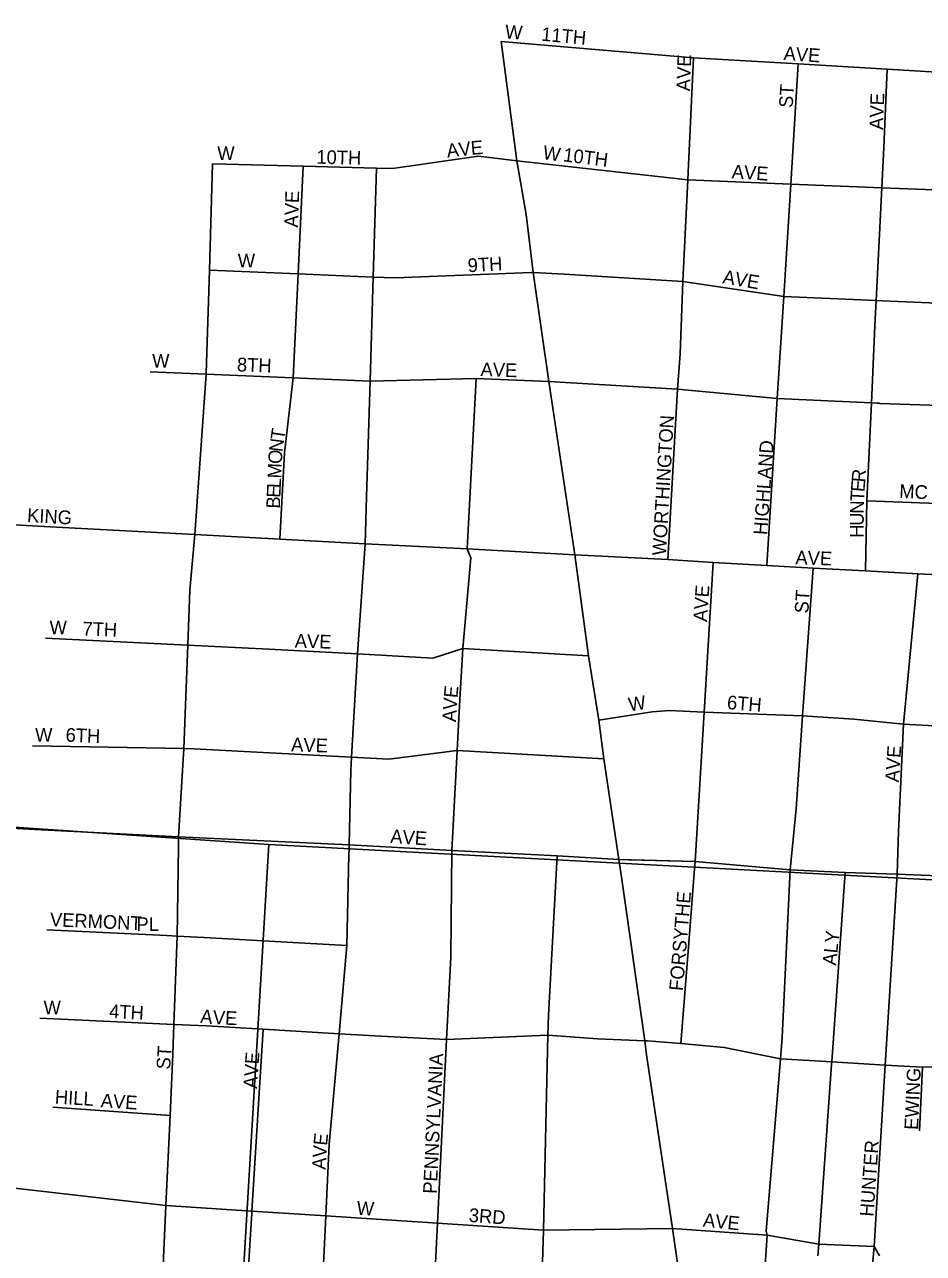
# Model space of a CAD drawing. Extents: x 0 to 34, y -6.2 to 22.
# Drawn here: x 5.605 to 6.226, y 19.522 to 20.371 of the extents above; entities that cross this region are included whole.
import ezdxf

# ---------------------------------------------------------------- set-up
doc = ezdxf.new("R2010")
doc.units = 0
for name, color, linetype in [('GM_X_City_Street', 7, 'Continuous'), ('GM_X_City_Street_Text', 7, 'Continuous'), ('GM_X_Section', 7, 'Continuous'), ('GM_X_Township', 7, 'Continuous')]:
    doc.layers.add(name, color=color, linetype=linetype)

msp = doc.modelspace()

# ---------------------------------------------------------------- linework, layer by layer
at = {"layer": 'GM_X_City_Street'}
for points in [[(5.93406, 20.35914), (6.06678, 20.34787), (6.13911, 20.34361), (6.20051, 20.34), (6.2726, 20.33575), (6.33393, 20.33936)], [(5.98498, 20.00452), (5.96693, 20.12437), (5.95608, 20.19966), (5.95115, 20.23962), (5.9449, 20.27677), (5.93406, 20.35914)], [(6.06323, 20.26861), (6.06324, 20.2688), (6.06678, 20.34787)], [(6.11749, 19.99729), (6.12365, 20.09765), (6.1246, 20.11246), (6.12917, 20.18309), (6.13011, 20.19779), (6.13399, 20.26068), (6.13911, 20.34361)], [(6.18555, 19.99351), (6.18662, 20.04188), (6.1897, 20.10947), (6.19212, 20.16267), (6.19301, 20.18015), (6.19696, 20.25815), (6.19836, 20.28588), (6.20051, 20.34)], [(5.73461, 20.27461), (5.79729, 20.27299), (5.84793, 20.27168), (5.85897, 20.27139), (5.91827, 20.2799), (5.9449, 20.27677)], [(5.71752, 19.94239), (5.7189, 19.98024), (5.72242, 20.0185), (5.73024, 20.12941), (5.7303, 20.13004), (5.73242, 20.20123), (5.73461, 20.27461)], [(5.78112, 20.01538), (5.78424, 20.07506), (5.79033, 20.12687), (5.79141, 20.15046), (5.79372, 20.19862), (5.79729, 20.27299)], [(5.82893, 19.80143), (5.82899, 19.80424), (5.83011, 19.85567), (5.83063, 19.86477), (5.83471, 19.9361), (5.84014, 20.01225), (5.84092, 20.04468), (5.84339, 20.12462), (5.8456, 20.19642), (5.84793, 20.27168)], [(5.9449, 20.27677), (6.063, 20.26353), (6.13399, 20.26068), (6.19696, 20.25815), (6.27488, 20.25503), (6.29146, 20.25437), (6.347, 20.25377)], [(6.0491, 20.00124), (6.05587, 20.11894), (6.05762, 20.14328), (6.05949, 20.19342), (6.063, 20.26353), (6.06323, 20.26861)], [(5.73242, 20.20123), (5.79372, 20.19862), (5.8456, 20.19642), (5.86069, 20.19578), (5.95487, 20.19962)], [(5.95487, 20.19962), (5.95608, 20.19966), (5.97779, 20.19835), (6.05949, 20.19342), (6.12917, 20.18309), (6.19301, 20.18015), (6.19741, 20.17995), (6.2888, 20.17613), (6.32406, 20.17906), (6.35834, 20.17633)], [(5.69151, 20.13105), (5.73024, 20.12941), (5.79033, 20.12687), (5.84339, 20.12462), (5.91663, 20.12634), (5.96693, 20.12437), (6.05587, 20.11894), (6.1246, 20.11246), (6.1897, 20.10947), (6.19355, 20.10929), (6.19503, 20.10922)], [(5.91096, 20.00762), (5.91051, 20.0088), (5.91663, 20.12634)], [(6.19503, 20.10922), (6.1956, 20.10919), (6.31996, 20.10504), (6.32849, 20.10459), (6.36985, 20.10251)], [(6.18662, 20.04188), (6.3273, 20.03664), (6.33713, 20.0356), (6.37955, 20.03379)], [(5.52466, 20.02932), (5.62247, 20.02392), (5.72242, 20.0185), (5.78112, 20.01538), (5.84014, 20.01225), (5.91051, 20.0088), (5.98498, 20.00452), (6.0491, 20.00124), (6.08033, 19.99927), (6.11749, 19.99729), (6.14955, 19.99532), (6.18555, 19.99351), (6.22189, 19.99138), (6.28403, 19.98841), (6.33647, 19.98562), (6.34387, 19.98545), (6.38744, 19.98332), (6.38733, 19.98465)], [(5.89998, 19.80023), (5.89998, 19.80029), (5.90365, 19.86939), (5.90534, 19.90472), (5.9076, 19.93976), (5.91293, 20.00248), (5.91096, 20.00762)], [(6.01654, 19.78521), (6.01527, 19.79408), (6.00491, 19.86363), (6.00146, 19.89042), (5.99439, 19.93481), (5.98498, 20.00452)], [(6.06755, 19.78773), (6.06794, 19.79284), (6.07411, 19.89588), (6.08033, 19.99927)], [(6.11013, 19.42037), (6.11769, 19.53465), (6.11702, 19.5375), (6.12683, 19.65653), (6.12803, 19.67119), (6.13371, 19.78691), (6.13774, 19.82919), (6.14222, 19.89329), (6.1429, 19.90306), (6.14955, 19.99532)], [(6.20854, 19.81362), (6.20872, 19.81845), (6.21182, 19.88765), (6.22189, 19.99138)], [(5.61931, 19.9469), (5.71751, 19.94214), (5.77341, 19.93942), (5.83471, 19.9361), (5.88681, 19.93329), (5.9076, 19.93976), (5.99439, 19.93481)], [(5.7111, 19.80291), (5.7112, 19.80977), (5.7149, 19.87069), (5.71751, 19.94214), (5.71752, 19.94239)], [(6.00146, 19.89042), (6.03826, 19.89613), (6.05036, 19.89707), (6.07411, 19.89588), (6.14222, 19.89329), (6.17763, 19.89114), (6.21182, 19.88765), (6.2765, 19.88421)], [(5.61036, 19.87256), (5.7149, 19.87069), (5.72176, 19.87056), (5.83063, 19.86477), (5.85647, 19.8634), (5.90365, 19.86939), (6.00491, 19.86363)], [(5.56099, 19.81796), (5.60742, 19.81518), (5.7112, 19.80977), (5.82899, 19.80424), (5.89998, 19.80029), (5.97269, 19.79671), (6.01527, 19.79408), (6.02212, 19.79392)], [(6.19163, 19.52685), (6.19923, 19.65216), (6.20742, 19.78399), (6.20854, 19.81362)], [(5.68704, 19.33828), (5.68474, 19.35251), (5.69726, 19.44412), (5.69975, 19.49822), (5.70237, 19.55511), (5.70524, 19.61733), (5.70718, 19.65961), (5.70793, 19.68021), (5.71016, 19.74121), (5.7111, 19.80291)], [(5.80328, 19.33157), (5.80735, 19.43507), (5.80749, 19.43811), (5.81279, 19.54792), (5.81519, 19.59744), (5.82202, 19.67375), (5.82748, 19.73461), (5.82884, 19.7976), (5.82893, 19.80143)], [(5.87759, 19.32494), (5.88394, 19.4339), (5.88816, 19.50638), (5.88998, 19.5429), (5.89628, 19.66973), (5.89911, 19.72675), (5.89998, 19.80023)], [(5.94754, 19.32792), (5.95666, 19.42961), (5.9616, 19.48602), (5.96318, 19.53814), (5.96627, 19.67275), (5.9666, 19.6864), (5.97269, 19.79671)], [(6.02212, 19.79392), (6.06794, 19.79284), (6.13371, 19.78691), (6.17169, 19.78524), (6.20742, 19.78399), (6.26956, 19.78144), (6.3756, 19.77496), (6.37911, 19.77474), (6.41449, 19.77342)], [(6.05818, 19.667), (6.06342, 19.73348), (6.06755, 19.78773)], [(6.19591, 18.56034), (6.19665, 18.59208), (6.20072, 18.6952), (6.20307, 18.75671), (6.20288, 18.76478), (6.1973, 18.78643), (6.19155, 18.79843), (6.17255, 18.82567), (6.16294, 18.83821), (6.15118, 18.86085), (6.1493, 18.86763), (6.13803, 18.94558), (6.12654, 19.0265), (6.11342, 19.1096), (6.10394, 19.17992), (6.09467, 19.24481), (6.08497, 19.31221), (6.07265, 19.3982), (6.06886, 19.42877), (6.06015, 19.48517), (6.05243, 19.53925), (6.03434, 19.65927), (6.03319, 19.66897), (6.01654, 19.78521)], [(6.16228, 19.65278), (6.1624, 19.65439), (6.17169, 19.78524)], [(5.6201, 19.74542), (5.703, 19.74154), (5.70307, 19.74154)], [(5.70307, 19.74154), (5.71016, 19.74121), (5.72373, 19.74057), (5.72382, 19.74057)], [(5.72382, 19.74057), (5.72891, 19.74032), (5.78598, 19.73702), (5.78601, 19.73702)], [(5.78601, 19.73702), (5.82748, 19.73461)], [(5.6154, 19.68449), (5.70793, 19.68021), (5.73068, 19.67916), (5.76958, 19.67686), (5.82202, 19.67375), (5.85095, 19.67204), (5.89628, 19.66973), (5.96627, 19.67275), (6.00047, 19.67029), (6.03319, 19.66897), (6.03505, 19.66882)], [(5.76168, 19.54919), (5.76181, 19.55124), (5.76958, 19.67686)], [(6.03505, 19.66882), (6.05818, 19.667), (6.0881, 19.66437), (6.12683, 19.65653), (6.1624, 19.65439), (6.19923, 19.65216), (6.22501, 19.65062), (6.26402, 19.65116)], [(6.15278, 19.52032), (6.15336, 19.52838), (6.16203, 19.6493), (6.16228, 19.65278)], [(6.22305, 19.60659), (6.22501, 19.65062)], [(5.6244, 19.62311), (5.70524, 19.61733)], [(5.50934, 19.57319), (5.53774, 19.57154), (5.5817, 19.56888), (5.70237, 19.55511), (5.76181, 19.55124), (5.81279, 19.54792), (5.88998, 19.5429), (5.96318, 19.53814), (6.05243, 19.53925), (6.11769, 19.53465), (6.15336, 19.52838), (6.19163, 19.52685), (6.19521, 19.52027)], [(5.74671, 19.33324), (5.75506, 19.441), (5.75897, 19.50531), (5.76151, 19.54644), (5.76168, 19.54919)], [(6.17141, 19.30272), (6.18167, 19.41647), (6.19163, 19.52685)]]:
    msp.add_lwpolyline(points, dxfattribs=at)
at = {"layer": 'GM_X_Section'}
for points in [[(5.77359, 19.80442), (5.74527, 19.32804), (5.23224, 19.35957), (4.71794, 19.38931), (4.75087, 19.87398)], [(5.77359, 19.80442), (6.48211, 19.76671), (6.79694, 19.75181), (6.76078, 19.26937), (6.54767, 19.28066), (6.25432, 19.30018), (5.74527, 19.32804)]]:
    msp.add_lwpolyline(points, close=True, dxfattribs=at)
at = {"layer": 'GM_X_Township'}
msp.add_lwpolyline([(5.42369, 19.82617), (5.60742, 19.81518), (5.7112, 19.80977), (5.82899, 19.80424), (5.89998, 19.80029), (5.97269, 19.79671), (6.01527, 19.79408), (6.06794, 19.79284), (6.1337, 19.7869), (6.17169, 19.78524), (6.20742, 19.78399), (6.26956, 19.78144)], dxfattribs=at)

# ---------------------------------------------------------------- texts
at = {"layer": 'GM_X_City_Street_Text'}
for s, height, rotation, p in [('W', 0.00947, 355.60387, (5.93638, 20.36138)), ('11TH', 0.00947, 354.64672, (5.96141, 20.35972)), ('AVE', 0.00947, 356.04938, (6.12886, 20.34639)), ('AVE', 0.00947, 87.9557, (6.06446, 20.32467)), ('ST', 0.00947, 86.42621, (6.1353, 20.31306)), ('AVE', 0.00947, 88.02609, (6.19779, 20.29801)), ('W', 0.00947, 0.00001, (5.73791, 20.27722)), ('A', 0.00947, 6.63706, (5.89685, 20.27888)), ('V', 0.00947, 6.66426, (5.90513, 20.27984)), ('E', 0.00947, 4.67742, (5.91332, 20.2808)), ('W', 0.00947, 351.25889, (5.96235, 20.27804)), ('10TH', 0.00947, 358.63682, (5.80628, 20.27473)), ('10TH', 0.00947, 352.87246, (5.97646, 20.27638)), ('AVE', 0.00947, 356.0499, (6.09303, 20.26472)), ('AVE', 0.00947, 88.02609, (5.79363, 20.23051)), ('W', 0.00947, 0.00001, (5.75207, 20.20306)), ('9TH', 0.00947, 3.27493, (5.91114, 20.19972)), ('AVE', 0.00947, 350.21532, (6.08654, 20.1922)), ('W', 0.00947, 0.00001, (5.69291, 20.13389)), ('8TH', 0.00947, 357.70206, (5.75131, 20.13139)), ('AVE', 0.00947, 358.02636, (5.91963, 20.12806)), ('WORTHINGTON', 0.0094697, 86.69785, (6.04779, 20.00388)), ('T', 0.00947, 81.52597, (5.78398, 20.08348)), ('N', 0.00947, 82.61475, (5.78292, 20.07526)), ('HIGHLAND', 0.00947, 86.08101, (6.1178, 20.01807)), ('O', 0.00947, 86.74135, (5.78246, 20.06712)), ('M', 0.00947, 87.50411, (5.78203, 20.05717)), ('R', 0.00947, 85.40574, (6.18543, 20.05438)), ('E', 0.00947, 87.51281, (5.78145, 20.04384)), ('L', 0.00947, 87.5405, (5.78174, 20.05051)), ('T', 0.00947, 86.7747, (6.18454, 20.04113)), ('E', 0.00947, 85.51539, (6.18491, 20.04774)), ('MC', 0.00947, 357.39924, (6.20882, 20.04389)), ('B', 0.00947, 87.52204, (5.78113, 20.03635)), ('N', 0.00947, 89.49721, (6.18447, 20.03292)), ('KING', 0.00947, 356.72507, (5.60634, 20.02723)), ('U', 0.00947, 89.95627, (6.18446, 20.02461)), ('H', 0.00947, 89.95627, (6.18446, 20.01628)), ('AVE', 0.00947, 358.0261, (6.13713, 19.99806)), ('AVE', 0.00947, 86.05688, (6.07613, 19.95807)), ('ST', 0.00947, 86.42535, (6.14613, 19.96389)), ('W', 0.00947, 0.00001, (5.62207, 19.94972)), ('7TH', 0.00947, 357.71044, (5.64465, 19.94889)), ('AVE', 0.00947, 358.01858, (5.7913, 19.94056)), ('E', 0.00947, 84.74618, (5.90375, 19.90541)), ('V', 0.00947, 86.43456, (5.90324, 19.89717)), ('W', 0.00947, 8.74111, (6.02264, 19.89637)), ('6TH', 0.00947, 355.42816, (6.08971, 19.89806)), ('A', 0.00947, 86.93897, (5.9028, 19.88887)), ('W', 0.00947, 0.00001, (5.61207, 19.87556)), ('6TH', 0.00947, 357.71044, (5.63298, 19.87556)), ('AVE', 0.00947, 358.0261, (5.7888, 19.86889)), ('AVE', 0.00947, 86.05688, (6.20863, 19.84724)), ('AVE', 0.00947, 356.05688, (5.8572, 19.80556)), ('FORSYTHE', 0.00947, 85.23585, (6.05947, 19.7031)), ('VERMONT', 0.00947, 357.51182, (5.62215, 19.74806)), ('PL', 0.00947, 0.00001, (5.68207, 19.74473)), ('ALY', 0.00947, 84.08948, (6.1653, 19.72063)), ('W', 0.00947, 0.00001, (5.61791, 19.68723)), ('4TH', 0.00947, 356.73129, (5.66301, 19.68472)), ('A', 0.00947, 353.97841, (5.72585, 19.68135)), ('V', 0.00947, 357.27925, (5.73473, 19.68043)), ('E', 0.00947, 357.59328, (5.74311, 19.68003)), ('ST', 0.00947, 86.42621, (5.7053, 19.64889)), ('AVE', 0.00947, 86.05688, (5.7653, 19.63557)), ('PENNSYLVANIA', 0.0094697, 87.32395, (5.88946, 19.56303)), ('EWING', 0.00947, 87.51188, (6.22196, 19.60719)), ('HILL', 0.00947, 356.42537, (5.62552, 19.62556)), ('AVE', 0.00947, 356.04938, (5.6572, 19.62306)), ('E', 0.00947, 84.08823, (5.81366, 19.5962)), ('HUNTER', 0.00947, 85.9166, (6.19113, 19.54724)), ('V', 0.00947, 86.98261, (5.81323, 19.58801)), ('A', 0.00947, 86.98261, (5.81279, 19.57968)), ('W', 0.00947, 355.60258, (5.83388, 19.54889)), ('3RD', 0.00947, 355.60387, (5.91138, 19.54389)), ('AVE', 0.00947, 354.09695, (6.07309, 19.54055))]:
    msp.add_text(s, height=height, rotation=rotation, dxfattribs=at).set_placement(p)

doc.saveas('drawing.dxf')
